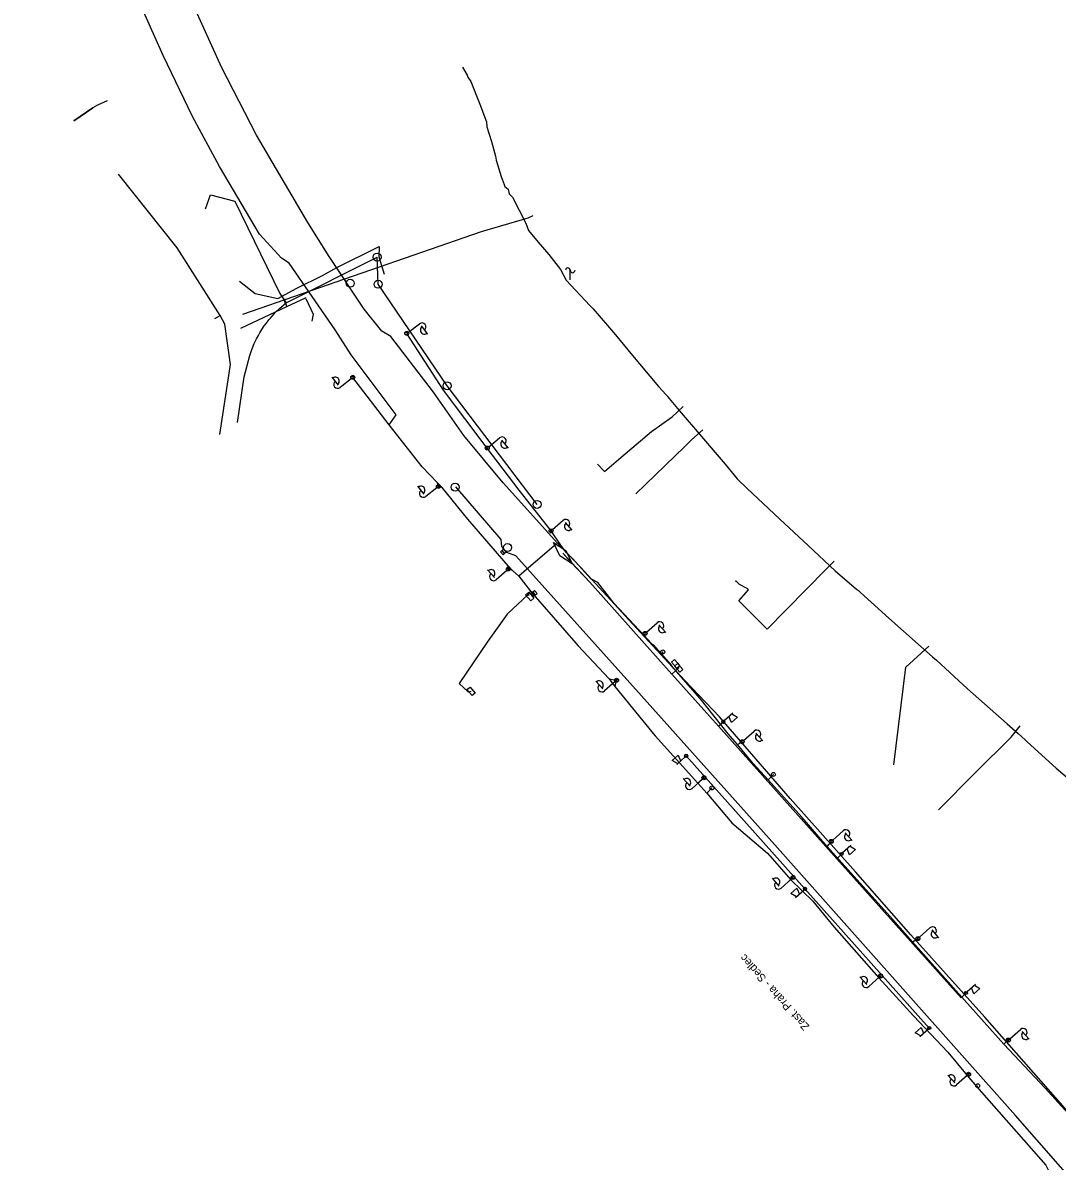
# Model space of a CAD drawing. Extents: x -748507 to -687366, y -1057342 to -1024924.
# Drawn here: x -744227.9 to -743969.6, y -1037925.9 to -1037641.4 of the extents above; entities that cross this region are included whole.
import ezdxf

# ---------------------------------------------------------------- set-up
doc = ezdxf.new("R2010")
doc.units = 0
for name, color, linetype in [('6kV - SŽDC', 7, 'Continuous'), ('DK + TKK - SŽDC', 7, 'Continuous'), ('Kanalizace - pražské vodovody a kanalizace', 7, 'Continuous'), ('kanalizace ČD', 7, 'Continuous'), ('Sděl MK - SŽDC', 7, 'Continuous'), ('Telefonica O2', 7, 'Continuous'), ('TK+DOK_Pha Holešovice - Kralupy', 7, 'Continuous'), ('Vedení NN - SŽDC', 7, 'Continuous'), ('Vodovod - přežsko vodovody a kanalizace', 7, 'Continuous'), ('Vrstva 14', 7, 'Continuous'), ('ČD-Telematika_DK+TKK', 7, 'Continuous')]:
    doc.layers.add(name, color=color, linetype=linetype)

msp = doc.modelspace()

# ---------------------------------------------------------------- linework, layer by layer
at = {"layer": '6kV - SŽDC'}
for points in [[(-744136.41, -1037741.88), (-744134.63, -1037739.35), (-744145.92, -1037724.4), (-744149.9, -1037718.14), (-744161.41, -1037701.48), (-744163.3, -1037700.18), (-744168.75, -1037694.21), (-744178.79, -1037677.28), (-744185.52, -1037664.81), (-744192.83, -1037649.54), (-744203.66, -1037625.26), (-744209.6, -1037609.61), (-744217.12, -1037587.03), (-744216.6, -1037581.64), (-744220.79, -1037565.26), (-744224.26, -1037550.1), (-744226.25, -1037538.68), (-744227.91, -1037530.73)], [(-743989.74, -1037907.17), (-743972.42, -1037926.86), (-743971.51, -1037928.66), (-743970.83, -1037928.59)]]:
    msp.add_lwpolyline(points, dxfattribs=at)
at = {"layer": 'DK + TKK - SŽDC'}
for points in [[(-743951, -1037932.72), (-743961.3, -1037920.58), (-743965.73, -1037914.79), (-743987.63, -1037889.86), (-744006.08, -1037869.33), (-744019.94, -1037853.55), (-744036.28, -1037835.25), (-744053.92, -1037814.83), (-744062.52, -1037805.73), (-744075.58, -1037791.7), (-744088.55, -1037777.53), (-744094.36, -1037771.44), (-744107.9, -1037756.32), (-744117.77, -1037744.56), (-744125.35, -1037733.66), (-744135.98, -1037719.81), (-744138.25, -1037718.44), (-744142.65, -1037712.92), (-744151.35, -1037699.75), (-744156.68, -1037691.33), (-744169.5, -1037669.51), (-744178.23, -1037652.65), (-744191.38, -1037623.6)], [(-744094.63, -1037771.59), (-744104.03, -1037779.65)]]:
    msp.add_lwpolyline(points, dxfattribs=at)
at = {"layer": 'Kanalizace - pražské vodovody a kanalizace'}
msp.add_line((-744162.15, -1037711.37), (-744139.36, -1037699.97), dxfattribs=at)
for points in [[(-744100.51, -1037689.6), (-744101.79, -1037690.2), (-744113.39, -1037693.6), (-744173.07, -1037714.3)], [(-744174.31, -1037741.24), (-744172.61, -1037729.89), (-744171.19, -1037724.5), (-744170.78, -1037723.27), (-744170.08, -1037721.56), (-744169.5, -1037720.34), (-744169.06, -1037719.53), (-744168.71, -1037718.9), (-744168.18, -1037718.03), (-744167.6, -1037717.15), (-744167.08, -1037716.43), (-744166.44, -1037715.61), (-744166.07, -1037715.17), (-744165.66, -1037714.68), (-744164.75, -1037713.71), (-744163.69, -1037712.68), (-744162.73, -1037711.84), (-744162.56, -1037711.71), (-744162.15, -1037711.37)]]:
    msp.add_lwpolyline(points, dxfattribs=at)
at = {"layer": 'kanalizace ČD'}
for p, q in [((-744065.87, -1037802.05), (-744070.53, -1037796.84)), ((-744065.78, -1037801.97), (-744070.44, -1037796.76))]:
    msp.add_line(p, q, dxfattribs=at)
for points in [[(-744099.47, -1037761.74), (-744121.94, -1037732.1), (-744139.16, -1037706.74), (-744139.4, -1037699.95)], [(-743949.52, -1037950.73), (-743963.98, -1037932.73), (-743980.01, -1037914.41), (-744006.76, -1037884.28), (-744040.1, -1037846.82), (-744073.37, -1037809.61), (-744104.79, -1037774.57), (-744106.99, -1037773.74), (-744108.26, -1037772.24), (-744108.47, -1037770.54), (-744119.79, -1037757.39)], [(-744107.56, -1037774.03), (-744107.94, -1037774.36), (-744108.59, -1037773.6), (-744107.83, -1037772.95), (-744107.18, -1037773.71), (-744107.56, -1037774.03), (-744108.21, -1037773.28)], [(-744100.48, -1037783.58), (-744100.1, -1037783.25), (-744099.44, -1037784.01), (-744100.2, -1037784.66), (-744100.85, -1037783.91), (-744100.48, -1037783.58), (-744099.82, -1037784.33)]]:
    msp.add_lwpolyline(points, dxfattribs=at)
for centre in [(-744139.4, -1037699.95), (-744146.13, -1037706.48), (-744139.16, -1037706.74), (-744121.94, -1037732.1), (-744119.93, -1037757.43), (-744099.47, -1037761.74), (-744106.84, -1037772.52)]:
    msp.add_circle(centre, 1, dxfattribs=at)
at = {"layer": 'Sděl MK - SŽDC'}
for p, q in [((-744053.29, -1037816.24), (-744052.61, -1037816.28)), ((-744053.28, -1037815.84), (-744052.58, -1037815.88)), ((-744050.57, -1037813.91), (-744052.66, -1037815.77)), ((-744050.92, -1037816.22), (-744051.54, -1037814.77)), ((-744049.43, -1037814.89), (-744050.92, -1037816.22)), ((-744050.8, -1037814.11), (-744049.43, -1037814.89)), ((-744065.74, -1037825.71), (-744064.25, -1037824.38)), ((-744064.59, -1037826.7), (-744062.51, -1037824.84)), ((-744064.25, -1037824.38), (-744063.62, -1037825.83)), ((-744061.89, -1037824.76), (-744062.58, -1037824.72)), ((-744061.87, -1037824.36), (-744062.56, -1037824.33)), ((-744064.37, -1037826.5), (-744065.74, -1037825.71)), ((-744021.06, -1037846.95), (-744023.14, -1037848.81)), ((-744021.28, -1037847.15), (-744019.91, -1037847.94)), ((-744023.78, -1037849.28), (-744023.1, -1037849.32)), ((-744023.76, -1037848.88), (-744023.07, -1037848.92)), ((-744021.4, -1037849.27), (-744022.03, -1037847.81)), ((-744019.91, -1037847.94), (-744021.4, -1037849.27)), ((-744036.06, -1037858.98), (-744034.57, -1037857.65)), ((-744034.69, -1037859.77), (-744036.06, -1037858.98)), ((-744034.91, -1037859.97), (-744032.83, -1037858.1)), ((-744034.57, -1037857.65), (-744033.94, -1037859.1)), ((-744032.2, -1037858.03), (-744032.9, -1037857.99)), ((-744032.19, -1037857.63), (-744032.87, -1037857.6)), ((-743989.99, -1037881.7), (-743992.08, -1037883.57)), ((-743992.71, -1037884.04), (-743992.03, -1037884.08)), ((-743992.7, -1037883.64), (-743992, -1037883.68)), ((-743990.34, -1037884.02), (-743990.96, -1037882.57)), ((-743988.85, -1037882.69), (-743990.34, -1037884.02)), ((-743990.22, -1037881.9), (-743988.85, -1037882.69)), ((-744005.03, -1037893.76), (-744003.53, -1037892.42)), ((-744003.88, -1037894.74), (-744001.79, -1037892.88)), ((-744003.53, -1037892.42), (-744002.91, -1037893.88)), ((-744001.17, -1037892.81), (-744001.87, -1037892.77)), ((-744001.16, -1037892.41), (-744001.84, -1037892.37)), ((-744003.65, -1037894.54), (-744005.03, -1037893.76))]:
    msp.add_line(p, q, dxfattribs=at)
for points in [[(-744090.72, -1037776.55), (-744093.78, -1037774.58), (-744095.34, -1037771.29), (-744092.28, -1037773.26), (-744090.72, -1037776.55)], [(-744063.98, -1037802.53), (-744065.79, -1037804.18), (-744086.3, -1037781.19), (-744091.07, -1037776.16), (-744093.03, -1037773.92)], [(-744093.03, -1037773.92), (-744086.3, -1037781.19), (-744065.79, -1037804.18), (-744063.98, -1037802.53)], [(-744065.79, -1037804.18), (-744054.17, -1037817.14), (-744024.61, -1037850.28)], [(-744054.17, -1037817.14), (-744052.93, -1037816.06)], [(-744001.5, -1037892.59), (-744032.55, -1037857.77), (-744062.2, -1037824.53)], [(-744024.61, -1037850.28), (-744023.43, -1037849.12)], [(-744024.61, -1037850.28), (-743993.55, -1037885.02)], [(-743993.55, -1037885.02), (-743992.37, -1037883.86)]]:
    msp.add_lwpolyline(points, dxfattribs=at)
for centre in [(-744052.94, -1037816.06), (-744052.94, -1037816.06), (-744062.23, -1037824.55), (-744062.23, -1037824.55), (-744023.43, -1037849.1), (-744023.43, -1037849.1), (-744032.54, -1037857.82), (-744032.54, -1037857.82), (-743992.36, -1037883.85), (-743992.36, -1037883.85), (-744001.51, -1037892.59), (-744001.51, -1037892.59)]:
    msp.add_circle(centre, 0.401, dxfattribs=at)
at = {"layer": 'Telefonica O2'}
for points in [[(-744206.8, -1037660.88), (-744209.26, -1037661.95), (-744210.45, -1037662.61), (-744215.15, -1037665.85)], [(-744215.15, -1037665.85), (-744210.45, -1037662.61)], [(-744178.6, -1037714.53), (-744189.31, -1037697.61), (-744204, -1037679.25)], [(-744173.81, -1037705.92), (-744169.84, -1037709.05), (-744164.17, -1037710.31), (-744159.44, -1037707.73), (-744153.05, -1037704.51), (-744149.45, -1037702.56), (-744138.87, -1037697.32)], [(-744138.87, -1037697.32), (-744139.02, -1037699.85), (-744137.62, -1037704.24)], [(-744179.97, -1037715.25), (-744178.6, -1037714.53)], [(-744178.71, -1037744.3), (-744176.05, -1037726.8), (-744177.41, -1037716.73), (-744178.6, -1037714.53)], [(-744084.41, -1037751.65), (-744082.65, -1037753.53), (-744078.51, -1037750), (-744070.89, -1037743.5), (-744065.72, -1037739.83), (-744062.96, -1037737.28)], [(-744058.07, -1037743.07), (-744060.86, -1037745.59), (-744062.75, -1037747.42), (-744064.92, -1037749.53), (-744067.55, -1037752.09), (-744074.79, -1037759.13)], [(-744049.09, -1037785.83), (-744042.01, -1037792.91), (-744027.37, -1037778.04), (-744025.28, -1037775.89)], [(-744049.09, -1037785.83), (-744046.65, -1037783.05), (-744046.97, -1037782.72), (-744048.88, -1037781.74), (-744049.81, -1037780.82), (-744050.01, -1037781.02)], [(-744010.38, -1037826.83), (-744007.38, -1037802.45), (-744001.58, -1037797.18)], [(-743999.2, -1037838.04), (-743990.06, -1037828.8), (-743981.04, -1037819.88), (-743978.82, -1037817.06)]]:
    msp.add_lwpolyline(points, dxfattribs=at)
at = {"layer": 'TK+DOK_Pha Holešovice - Kralupy'}
for points in [[(-744075.57, -1037791.7), (-744088.55, -1037777.53), (-744094.36, -1037771.44), (-744107.9, -1037756.32), (-744117.77, -1037744.56), (-744125.35, -1037733.66), (-744135.98, -1037719.81), (-744138.25, -1037718.44), (-744142.65, -1037712.92), (-744151.35, -1037699.75), (-744156.68, -1037691.33), (-744169.5, -1037669.51), (-744178.23, -1037652.65), (-744191.38, -1037623.6), (-744198.95, -1037603.56), (-744204.71, -1037585.87), (-744213.17, -1037555.37), (-744215.93, -1037543.56), (-744219.63, -1037523.93), (-744221.08, -1037514.2)], [(-743951, -1037932.72), (-743961.3, -1037920.58), (-743965.73, -1037914.79), (-743987.63, -1037889.87), (-744006.08, -1037869.33), (-744019.94, -1037853.55), (-744036.28, -1037835.25), (-744053.92, -1037814.83), (-744062.52, -1037805.73), (-744075.57, -1037791.7), (-744088.55, -1037777.53), (-744094.36, -1037771.44), (-744107.9, -1037756.32), (-744117.77, -1037744.56), (-744125.35, -1037733.66), (-744135.98, -1037719.81), (-744138.25, -1037718.44), (-744142.65, -1037712.92), (-744151.35, -1037699.75), (-744156.68, -1037691.33), (-744169.5, -1037669.51), (-744178.23, -1037652.65), (-744191.38, -1037623.6)], [(-743951, -1037932.72), (-743961.3, -1037920.58), (-743965.73, -1037914.79), (-743987.63, -1037889.87), (-744006.08, -1037869.33), (-744019.94, -1037853.55), (-744036.28, -1037835.25), (-744053.92, -1037814.83), (-744062.52, -1037805.73), (-744075.57, -1037791.7)]]:
    msp.add_lwpolyline(points, dxfattribs=at)
at = {"layer": 'Vedení NN - SŽDC'}
for p, q in [((-744131.6, -1037718.71), (-744128.82, -1037716.58)), ((-744132.49, -1037719.09), (-744131.54, -1037719.21)), ((-744132.41, -1037718.72), (-744131.53, -1037718.84)), ((-744128.4, -1037717.14), (-744126.82, -1037719.21)), ((-744149.05, -1037731.96), (-744150.67, -1037729.92)), ((-744145.88, -1037730.33), (-744148.62, -1037732.51)), ((-744145, -1037729.93), (-744145.95, -1037729.82)), ((-744145.08, -1037730.3), (-744145.95, -1037730.2)), ((-744111.51, -1037747.33), (-744108.81, -1037745.11)), ((-744112.39, -1037747.74), (-744111.44, -1037747.84)), ((-744112.32, -1037747.37), (-744111.44, -1037747.46)), ((-744108.37, -1037745.65), (-744106.71, -1037747.65)), ((-744127.66, -1037759.2), (-744129.28, -1037757.16)), ((-744124.48, -1037757.56), (-744127.22, -1037759.74)), ((-744123.6, -1037757.17), (-744124.56, -1037757.06)), ((-744123.68, -1037757.54), (-744124.56, -1037757.44)), ((-744095.58, -1037768.02), (-744092.94, -1037765.72)), ((-744092.48, -1037766.25), (-744090.78, -1037768.21)), ((-744096.45, -1037768.46), (-744095.49, -1037768.52)), ((-744096.38, -1037768.09), (-744095.51, -1037768.15)), ((-744110.13, -1037780.02), (-744111.84, -1037778.07)), ((-744107.04, -1037778.24), (-744109.66, -1037780.55)), ((-744106.17, -1037777.8), (-744107.13, -1037777.74)), ((-744106.23, -1037778.17), (-744107.11, -1037778.11)), ((-744072.09, -1037793.64), (-744069.49, -1037791.3)), ((-744069.02, -1037791.83), (-744067.29, -1037793.76)), ((-744072.95, -1037794.08), (-744072, -1037794.14)), ((-744072.9, -1037793.71), (-744072.02, -1037793.76)), ((-744068.11, -1037798.6), (-744068.01, -1037798.6)), ((-744083.06, -1037807.82), (-744084.79, -1037805.88)), ((-744079.98, -1037806.01), (-744082.59, -1037808.34)), ((-744079.12, -1037805.57), (-744080.08, -1037805.51)), ((-744079.18, -1037805.94), (-744080.06, -1037805.89)), ((-744047.87, -1037820.72), (-744045.26, -1037818.39)), ((-744044.79, -1037818.91), (-744043.06, -1037820.85)), ((-744048.72, -1037821.17), (-744047.77, -1037821.22)), ((-744048.67, -1037820.8), (-744047.79, -1037820.84)), ((-744061.22, -1037832.19), (-744062.96, -1037830.25)), ((-744058.15, -1037830.38), (-744060.76, -1037832.71)), ((-744057.29, -1037829.94), (-744058.25, -1037829.88)), ((-744057.35, -1037830.31), (-744058.23, -1037830.26)), ((-744040.47, -1037829.23), (-744040.37, -1037829.23)), ((-744055.85, -1037832.6), (-744055.75, -1037832.6)), ((-744025.61, -1037845.62), (-744023, -1037843.29)), ((-744022.53, -1037843.81), (-744020.8, -1037845.75)), ((-744026.46, -1037846.07), (-744025.51, -1037846.12)), ((-744026.41, -1037845.69), (-744025.53, -1037845.74)), ((-744038.97, -1037857.1), (-744040.7, -1037855.16)), ((-744035.9, -1037855.29), (-744038.51, -1037857.62)), ((-744035.04, -1037854.85), (-744035.99, -1037854.79)), ((-744035.1, -1037855.22), (-744035.97, -1037855.17)), ((-744003.97, -1037869.9), (-744001.36, -1037867.57)), ((-744004.83, -1037870.34), (-744003.87, -1037870.4)), ((-744004.77, -1037869.97), (-744003.89, -1037870.02)), ((-744000.89, -1037868.09), (-743999.16, -1037870.03)), ((-744017.1, -1037881.72), (-744018.83, -1037879.78)), ((-744014.02, -1037879.91), (-744016.63, -1037882.24)), ((-744013.16, -1037879.46), (-744014.12, -1037879.41)), ((-744013.22, -1037879.84), (-744014.1, -1037879.79)), ((-743981.37, -1037895.27), (-743978.76, -1037892.94)), ((-743982.23, -1037895.71), (-743981.27, -1037895.77)), ((-743982.17, -1037895.34), (-743981.29, -1037895.39)), ((-743978.29, -1037893.46), (-743976.56, -1037895.41)), ((-743995.16, -1037906.28), (-743996.89, -1037904.34)), ((-743992.08, -1037904.47), (-743994.69, -1037906.8)), ((-743991.22, -1037904.03), (-743992.18, -1037903.97)), ((-743991.28, -1037904.4), (-743992.16, -1037904.35)), ((-743989.44, -1037907.03), (-743989.34, -1037907.03))]:
    msp.add_line(p, q, dxfattribs=at)
for points in [[(-744095.96, -1037768.35), (-744103.94, -1037758.16), (-744111.9, -1037747.65), (-744122.85, -1037733.18), (-744132, -1037719.01)], [(-744124.33, -1037756.34), (-744128.14, -1037752.38), (-744136.41, -1037741.88), (-744145.5, -1037730.04)], [(-744105.58, -1037778.29), (-744106.7, -1037777.09), (-744116.77, -1037765.45), (-744123.19, -1037757.52), (-744124.33, -1037756.34)], [(-744123.19, -1037757.52), (-744124.13, -1037757.22), (-744124.33, -1037756.34)], [(-744072.69, -1037794.5), (-744080.18, -1037786.48), (-744084.28, -1037781.23), (-744086.05, -1037780.32), (-744090.57, -1037775.34), (-744092.09, -1037773.85), (-744093.55, -1037771.94), (-744095.96, -1037768.35)], [(-744105.58, -1037778.29), (-744106.66, -1037777.93), (-744106.7, -1037777.09)], [(-744104.03, -1037779.65), (-744105.58, -1037778.29)], [(-744104.03, -1037779.65), (-744101.13, -1037783.41), (-744101.69, -1037784.23), (-744101.49, -1037784.51)], [(-744101.69, -1037784.23), (-744106.9, -1037789.13), (-744111.95, -1037796.19), (-744118.88, -1037806.51), (-744116.68, -1037808.55), (-744115.93, -1037808.45)], [(-744100.24, -1037785.2), (-744100.99, -1037785.86), (-744102.32, -1037784.36), (-744101.56, -1037783.7), (-744100.24, -1037785.2)], [(-744101.13, -1037783.41), (-744089.22, -1037797.11), (-744081.45, -1037805.29), (-744080.04, -1037807.23)], [(-744049.42, -1037821.73), (-744051.74, -1037819.04), (-744058.69, -1037810.25), (-744068.13, -1037799.5), (-744072.69, -1037794.5)], [(-744068.13, -1037799.5), (-744068.06, -1037798.6)], [(-744063.82, -1037801.96), (-744064.57, -1037802.63), (-744065.9, -1037801.14), (-744065.15, -1037800.47), (-744063.82, -1037801.96)], [(-744063.04, -1037803), (-744063.78, -1037803.66), (-744065.11, -1037802.17), (-744064.37, -1037801.51), (-744063.04, -1037803)], [(-744114.89, -1037808.87), (-744115.65, -1037809.53), (-744116.97, -1037808.03), (-744116.21, -1037807.37), (-744114.89, -1037808.87)], [(-744081.45, -1037805.29), (-744079.71, -1037805.63), (-744080.04, -1037807.23), (-744070.47, -1037818.98), (-744070, -1037819.59), (-744059.28, -1037831.43), (-744057.05, -1037833.94)], [(-744049.42, -1037821.73), (-744048.23, -1037821.04)], [(-744045.47, -1037826.45), (-744049.42, -1037821.73)], [(-744027.01, -1037847.25), (-744033.26, -1037839.99), (-744041.74, -1037830.59), (-744045.47, -1037826.45)], [(-744059.28, -1037831.43), (-744057.8, -1037830.01)], [(-744041.74, -1037830.59), (-744040.42, -1037829.23)], [(-744057.05, -1037833.94), (-744055.8, -1037832.6)], [(-744057.05, -1037833.94), (-744050.84, -1037841.32), (-744041.9, -1037848.9), (-744036.05, -1037855.53)], [(-744027.01, -1037847.25), (-744025.95, -1037845.96)], [(-744010.59, -1037865.46), (-744027.01, -1037847.25)], [(-744036.05, -1037855.53), (-744035.55, -1037854.98)], [(-744036.05, -1037855.53), (-744030.57, -1037860.9), (-744025.25, -1037867.39), (-744014.09, -1037880.03), (-744013.67, -1037879.55)], [(-743982.9, -1037896.66), (-743992.68, -1037885.59), (-744005.68, -1037871.09), (-744010.59, -1037865.46)], [(-744005.68, -1037871.09), (-744004.29, -1037870.24)], [(-744014.09, -1037880.03), (-744005.45, -1037889.51), (-743996.91, -1037898.64), (-743992, -1037904.44), (-743991.68, -1037904.14)], [(-743982.9, -1037896.66), (-743981.72, -1037895.57)], [(-743955.58, -1037924.89), (-743957.86, -1037923.74), (-743961.12, -1037920.13), (-743963.55, -1037917.5), (-743972.55, -1037907.63), (-743982.9, -1037896.66)], [(-743992, -1037904.44), (-743989.74, -1037907.17), (-743989.39, -1037907.03)]]:
    msp.add_lwpolyline(points, dxfattribs=at)
for centre in [(-744132, -1037719.01), (-744132, -1037719.01), (-744145.49, -1037730.01), (-744145.49, -1037730.01), (-744111.9, -1037747.65), (-744111.9, -1037747.65), (-744124.09, -1037757.25), (-744124.09, -1037757.25), (-744095.96, -1037768.35), (-744095.96, -1037768.35), (-744106.66, -1037777.91), (-744106.66, -1037777.91), (-744072.47, -1037793.97), (-744072.47, -1037793.97), (-744068.06, -1037798.6), (-744079.61, -1037805.68), (-744079.61, -1037805.68), (-744048.24, -1037821.05), (-744048.24, -1037821.05), (-744057.78, -1037830.05), (-744057.78, -1037830.05), (-744040.42, -1037829.23), (-744055.8, -1037832.6), (-744025.98, -1037845.95), (-744025.98, -1037845.95), (-744035.52, -1037854.96), (-744035.52, -1037854.96), (-744004.34, -1037870.23), (-744004.34, -1037870.23), (-744013.65, -1037879.58), (-744013.65, -1037879.58), (-743981.74, -1037895.6), (-743981.74, -1037895.6), (-743991.71, -1037904.14), (-743991.71, -1037904.14), (-743989.39, -1037907.03)]:
    msp.add_circle(centre, 0.5, dxfattribs=at)
for centre, start, end in [((-744128.21, -1037717.38), 307.3279, 127.3279), ((-744127.62, -1037718.18), 126.6253, 308.0305), ((-744149.85, -1037730.93), 307.8342, 129.2394), ((-744149.24, -1037731.72), 128.5368, 308.5368), ((-744108.18, -1037745.88), 309.4737, 129.4737), ((-744107.55, -1037746.66), 128.7712, 310.1763), ((-744128.46, -1037758.17), 307.8342, 129.2394), ((-744127.85, -1037758.96), 128.5368, 308.5368), ((-744092.29, -1037766.48), 311.0605, 131.0605), ((-744091.64, -1037767.24), 130.3579, 311.763), ((-744110.97, -1037779.04), 310.6121, 132.0172), ((-744110.32, -1037779.8), 131.3146, 311.3146), ((-744068.82, -1037792.05), 311.8045, 131.8045), ((-744068.16, -1037792.8), 131.102, 312.5071), ((-744083.91, -1037806.84), 311.0617, 132.4669), ((-744083.26, -1037807.6), 131.7643, 311.7643), ((-744044.59, -1037819.13), 311.7832, 131.7832), ((-744043.93, -1037819.89), 131.0807, 312.4858), ((-744062.08, -1037831.22), 311.0617, 132.4669), ((-744061.42, -1037831.97), 131.7643, 311.7643), ((-744022.33, -1037844.04), 311.7447, 131.7447), ((-744021.67, -1037844.79), 131.0421, 312.4473), ((-744039.83, -1037856.12), 311.0538, 132.4589), ((-744039.17, -1037856.88), 131.7563, 311.7563), ((-744000.69, -1037868.31), 311.7544, 131.7544), ((-744000.04, -1037869.07), 131.0518, 312.457), ((-744017.95, -1037880.74), 311.0614, 132.4665), ((-744017.3, -1037881.5), 131.7639, 311.7639), ((-743978.09, -1037893.69), 311.6812, 131.6812), ((-743977.44, -1037894.44), 130.9786, 312.3838), ((-743996.02, -1037905.3), 311.0243, 132.4295), ((-743995.36, -1037906.05), 131.7269, 311.7269)]:
    msp.add_arc(centre, 1, start, end, dxfattribs=at)
at = {"layer": 'Vodovod - přežsko vodovody a kanalizace'}
for p, q in [((-744163.69, -1037709.02), (-744162.15, -1037711.37)), ((-744162.03, -1037712.04), (-744163.22, -1037709.49)), ((-744161.92, -1037712.28), (-744162.03, -1037712.04))]:
    msp.add_line(p, q, dxfattribs=at)
for points in [[(-744182.31, -1037687.88), (-744181, -1037684.38), (-744174.91, -1037685.99), (-744163.69, -1037709.02)], [(-744173.48, -1037717.68), (-744161.92, -1037712.28), (-744157.32, -1037710.1), (-744157.22, -1037710.04)], [(-744157.23, -1037710.29), (-744155.4, -1037714.17), (-744155.74, -1037715.97)]]:
    msp.add_lwpolyline(points, dxfattribs=at)
at = {"layer": 'ČD-Telematika_DK+TKK'}
msp.add_line((-744091.17, -1037705.62), (-744091.17, -1037703.24), dxfattribs=at)
for points in [[(-744118.06, -1037652.5), (-744116.89, -1037654.48), (-744116.77, -1037654.98), (-744116, -1037656.04), (-744113.77, -1037661.71), (-744112.08, -1037666.11), (-744111.97, -1037667.4), (-744110.83, -1037671.08), (-744109.84, -1037674.74), (-744109.67, -1037675.69), (-744108.47, -1037679.79), (-744107.68, -1037681.77), (-744107.52, -1037682.28), (-744106.67, -1037682.98), (-744106.46, -1037684.1)], [(-744106.46, -1037684.1), (-744105.63, -1037684.97), (-744102.27, -1037691.42), (-744101.64, -1037693.32), (-744099.2, -1037696.19), (-744096.56, -1037699.26), (-744093.61, -1037703.04)], [(-744093.61, -1037703.04), (-744092.18, -1037705.71), (-744086.28, -1037712.01), (-744085.48, -1037712.83), (-744079.89, -1037719.4), (-744076.07, -1037723.99), (-744069.16, -1037732.29), (-744067.19, -1037734.34), (-744067.01, -1037734.58), (-744066.85, -1037734.78), (-744063.94, -1037738.26), (-744061.49, -1037741.18), (-744060.93, -1037741.87), (-744052.46, -1037751.65), (-744049.51, -1037755.32), (-744047.02, -1037757.79), (-744044.35, -1037760.25), (-744043.01, -1037761.5), (-744038.85, -1037765.39), (-744031.75, -1037771.98), (-744025.04, -1037778.3), (-744019.66, -1037782.93), (-744019.21, -1037783.28), (-744018.69, -1037783.74), (-744011.6, -1037790.19), (-744003.51, -1037797.32), (-744000.68, -1037799.87), (-744000.24, -1037800.26), (-743999.73, -1037800.66), (-743991.97, -1037807.8), (-743982.08, -1037816.58), (-743979.29, -1037818.95), (-743977.55, -1037820.57), (-743977.04, -1037821.05), (-743969.78, -1037827.62), (-743961.47, -1037834.75)]]:
    msp.add_lwpolyline(points, dxfattribs=at)
for centre, start, end in [((-744091.76, -1037703.24), 0, 180), ((-744090.58, -1037703.24), 180, 0)]:
    msp.add_arc(centre, 0.594, start, end, dxfattribs=at)

# ---------------------------------------------------------------- texts
at = {"layer": 'Vrstva 14'}
msp.add_text('Zast. Praha - Sedlec', height=2, rotation=131.7615, dxfattribs=at).set_placement((-744031.3, -1037892.11))

doc.saveas('drawing.dxf')
